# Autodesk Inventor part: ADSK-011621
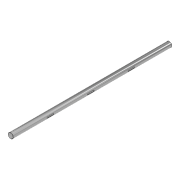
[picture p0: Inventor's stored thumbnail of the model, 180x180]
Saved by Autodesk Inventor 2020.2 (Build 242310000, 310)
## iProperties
Created: 2000-02
Part Number: ADSK-011621
Material: Pearson CD 1018
Document SubType Name: Modeling
Designer: sspink
Density: 7.83 g/cm^3
Appearance: Chrom - poliert
Mass: 2854.69 g
Surface Area: 597.524 cm^2
Volume: 364.583 cm^3
Control State: 0
Master: False
Checked Out: False
Shininess: 60.0
Length Units: 11269
Angle Units: 11279
Time Units: 11290
Mass Units: 11283
Length Display Precision: 3
Angle Display Precision: 2
Compacted: True
Cutlength: 23.25
Material Desc: Material Description goes here
Material_Number: Pearson
Dimensions: 25x745x25 mm
Mass: 2,855 kg
DocNumber: ADSK-011621.ipt
Folder: 01 - Themengebiete\Simplification\01 - Packaging machine\
VDS_Category: 3D Komponenten
VLT_Material: Pearson CD 1018
Density: 7.830000000000001
Volumn: 386.1110990722932
Area: 618.1831244989472
PropertySet Name: Model Information
Author: sspink
Revision Number: -
Title: shaft
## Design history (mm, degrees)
node "Solide1"
  node "Extrusion1" dims "d1" = 745, "d2" = 0
  node "Chamfer1" dims "d3" = 1, "d4" = 45 deg, "d7" = 0.762
  node "Chamfer2" dims "d5" = 1, "d6" = 45 deg, "d8" = 0.762
sketch "Sketch1"
  geometry: C1 r 12.5 at (0, 0); 1 further point
  constraints: 1 centre point, 1 coincident
  dimensions: "d0" = 25 diameter of C1
workplane "Arbeitsebene1"
sketch "Skizze2"
  geometry: L1 (0, 211.5)-(0, 185.5); L2 (-3, 211.5)-(-3, 185.5); L3 (3, 185.5)-(3, 211.5); L4 (-12.5, 372.5)-(12.5, 372.5) reference; L5 (0, -168.5)-(0, -194.5); L6 (-3, -168.5)-(-3, -194.5); L7 (3, -194.5)-(3, -168.5); L8 (0, 21.5)-(0, -4.5); L9 (-3, 21.5)-(-3, -4.5); L10 (3, -4.5)-(3, 21.5); A1 r 3 centre (0, 211.5) between (3, 211.5) and (-3, 211.5); A2 r 3 centre (0, 185.5) between (-3, 185.5) and (3, 185.5); A3 r 3 centre (0, -168.5) between (3, -168.5) and (-3, -168.5); A4 r 3 centre (0, -194.5) between (-3, -194.5) and (3, -194.5); A5 r 3 centre (0, 21.5) between (3, 21.5) and (-3, 21.5); A6 r 3 centre (0, -4.5) between (-3, -4.5) and (3, -4.5); 5 further points
  constraints: 26 end point, 12 point on circle, 12 tangent, 6 centre point, 4 midpoint, 3 parallel, 3 vertical, 3 vertical alignment, 1 horizontal, 2 other
  dimensions: "d9" = 26 distance of L1.start L1.end; "d10" = 161 distance from line of L4 L1.start; "d11" = 6 distance between parallel lines of L2 L3; "d12" = 26 distance of L5.start L5.end (= d9); "d13" = 6 distance between parallel lines of L6 L7; "d14" = 26 distance of L8.start L8.end (= d9); "d15" = 6 distance between parallel lines of L9 L10; "d16" = 190 distance of L1.start L8.start; "d17" = 190 distance of L5.start L8.start (= d16)
extrude "Extrusion2" cut sketch "Skizze2" distance "d18" = 2; taper "d19" = 0 deg
node "Corps solides"
node "Corps surfaciques"
